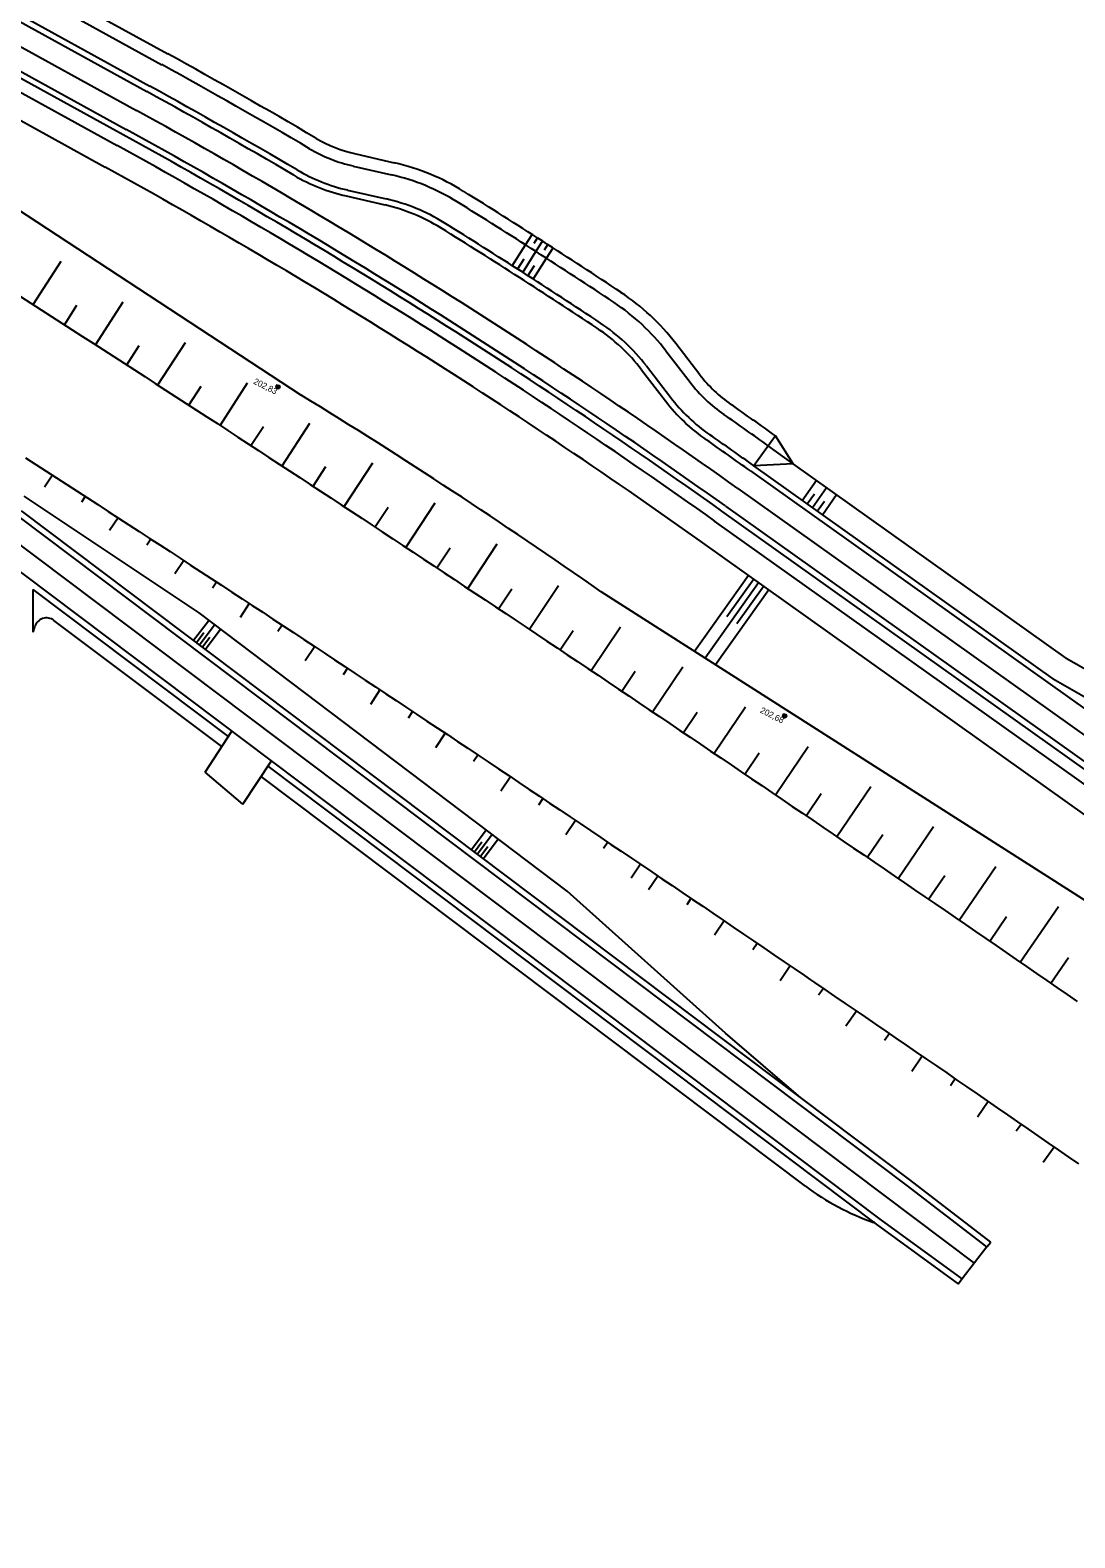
# Model space of a CAD drawing. Extents: x -552278 to -547230, y -1151007 to -1148251.
# Drawn here: x -550262.6 to -550177.8, y -1149150.6 to -1149028.3 of the extents above; entities that cross this region are included whole.
import ezdxf

# ---------------------------------------------------------------- set-up
doc = ezdxf.new("R2010")
doc.units = 0
doc.layers.add('SO221815_VYSKOPIS', color=7, linetype='Continuous')
doc.layers.add('u_trat navrh', color=7, linetype='Continuous')

# ---------------------------------------------------------------- blocks, each defined once
blk = doc.blocks.new('SO221824_VYSKOPIS')
at = {"layer": 'SO221815_VYSKOPIS'}
for p, q in [((1.2, -0.9), (-1.2, 0.9)), ((0.9, 1.2), (-0.9, -1.2)), ((0.9, 1.2), (0, 0)), ((0, 0), (1.2, -0.9))]:
    blk.add_line(p, q, dxfattribs=at)
blk.add_lwpolyline([(-0.9, -1.2), (0, 0), (-1.2, 0.9)], dxfattribs=at)
blk.add_circle((0, 0), 1.5, dxfattribs=at)
for start, end in [(145.362, 235.1538), (325.362, 55.1538)]:
    blk.add_arc((0, 0), 1.5, start, end, dxfattribs=at)

msp = doc.modelspace()

# ---------------------------------------------------------------- linework, layer by layer
at = {"layer": 'u_trat navrh'}
for p, q in [((-550460.23, -1148921.16), (-550253.98, -1149034.78)), ((-550461.07, -1148922.69), (-550254.82, -1149036.32)), ((-550461.8, -1148924.01), (-550255.55, -1149037.63)), ((-550462.76, -1148925.76), (-550256.51, -1149039.38)), ((-550441.65, -1148926.54), (-550251.93, -1149031.06)), ((-550442.86, -1148928.73), (-550253.14, -1149033.25)), ((-550442.62, -1148928.29), (-550252.89, -1149032.81)), ((-550371.01, -1148964.32), (-550251.45, -1149030.19)), ((-550236.18, -1149038.31), (-550233.06, -1149039.03)), ((-550268.44, -1149039.66), (-550240.61, -1149057.89)), ((-550236.4, -1149039.29), (-550233.28, -1149040)), ((-550236.85, -1149041.24), (-550233.73, -1149041.95)), ((-550236.96, -1149041.72), (-550233.84, -1149042.44)), ((-550222.41, -1149045.69), (-550221.87, -1149044.85)), ((-550223.48, -1149047.38), (-550222.41, -1149045.69)), ((-550221.71, -1149045.54), (-550221.44, -1149045.12)), ((-550221.56, -1149046.23), (-550221.02, -1149045.39)), ((-550220.87, -1149046.09), (-550220.6, -1149045.67)), ((-550220.72, -1149046.78), (-550220.17, -1149045.94)), ((-550262.36, -1149050.54), (-550260.09, -1149047)), ((-550223.06, -1149047.65), (-550222.52, -1149046.81)), ((-550222.64, -1149047.92), (-550221.56, -1149046.23)), ((-550222.22, -1149048.19), (-550221.68, -1149047.35)), ((-550221.8, -1149048.46), (-550220.72, -1149046.78)), ((-550259.83, -1149052.17), (-550258.81, -1149050.58)), ((-550257.3, -1149053.8), (-550255.05, -1149050.3)), ((-550254.77, -1149055.43), (-550253.76, -1149053.86)), ((-550252.25, -1149057.06), (-550250, -1149053.6)), ((-550211.02, -1149054.29), (-550209.06, -1149056.83)), ((-550210.22, -1149053.68), (-550208.27, -1149056.22)), ((-550213, -1149055.82), (-550211.04, -1149058.36)), ((-550212.6, -1149055.51), (-550210.65, -1149058.05)), ((-550249.73, -1149058.7), (-550248.72, -1149057.15)), ((-550247.2, -1149060.34), (-550244.96, -1149056.9)), ((-550244.69, -1149061.98), (-550243.68, -1149060.44)), ((-550242.17, -1149063.63), (-550239.9, -1149060.16)), ((-550202.13, -1149061.19), (-550203.87, -1149063.63)), ((-550200.68, -1149063.45), (-550202.71, -1149062)), ((-550200.68, -1149063.45), (-550202.13, -1149061.19)), ((-550260.81, -1149064.39), (-550261.45, -1149065.35)), ((-550239.65, -1149065.28), (-550238.61, -1149063.69)), ((-550237.14, -1149066.93), (-550234.79, -1149063.37)), ((-550204.16, -1149064.04), (-550115.93, -1149126.87)), ((-550200.68, -1149063.45), (-550203.87, -1149063.63)), ((-550179.6, -1149080.92), (-550203.87, -1149063.63)), ((-550178.52, -1149079.23), (-550200.68, -1149063.45)), ((-550205.18, -1149065.46), (-550087.55, -1149149.22)), ((-550199.95, -1149066.43), (-550198.79, -1149064.8)), ((-550199.13, -1149067.01), (-550197.97, -1149065.38)), ((-550248.9, -1149075.55), (-550263.1, -1149066.08)), ((-550258.14, -1149066.12), (-550258.44, -1149066.57)), ((-550234.63, -1149068.59), (-550233.56, -1149066.97)), ((-550232.12, -1149070.25), (-550229.73, -1149066.63)), ((-550206.19, -1149066.89), (-550088.57, -1149150.65)), ((-550199.54, -1149066.72), (-550198.96, -1149065.9)), ((-550198.73, -1149067.3), (-550198.15, -1149066.48)), ((-550198.32, -1149067.59), (-550197.16, -1149065.96)), ((-550191.52, -1149121.99), (-550263.62, -1149067.69)), ((-550191.22, -1149121.59), (-550263.32, -1149067.29)), ((-550255.47, -1149067.85), (-550256.16, -1149068.88)), ((-550144.16, -1149112.9), (-550207.06, -1149068.11)), ((-550185.98, -1149128.35), (-550264.54, -1149069.19)), ((-550193.63, -1149124.78), (-550265.73, -1149070.49)), ((-550252.81, -1149069.58), (-550253.13, -1149070.06)), ((-550229.61, -1149071.91), (-550228.53, -1149070.28)), ((-550227.1, -1149073.57), (-550224.71, -1149069.96)), ((-550140.95, -1149117.65), (-550208.22, -1149069.74)), ((-550250.15, -1149071.32), (-550250.87, -1149072.4)), ((-550247.49, -1149073.06), (-550247.82, -1149073.56)), ((-550204.3, -1149072.53), (-550208.69, -1149078.69)), ((-550203.49, -1149073.11), (-550207.84, -1149079.23)), ((-550203.89, -1149072.82), (-550206.08, -1149075.89)), ((-550246.51, -1149085.59), (-550262.36, -1149073.65)), ((-550262.36, -1149077.12), (-550262.36, -1149073.65)), ((-550224.6, -1149075.23), (-550223.52, -1149073.62)), ((-550222.1, -1149076.9), (-550219.72, -1149073.35)), ((-550166.24, -1149105.78), (-550216.28, -1149073.84)), ((-550202.67, -1149073.69), (-550207, -1149079.77)), ((-550203.08, -1149073.4), (-550205.25, -1149076.45)), ((-550219.03, -1149098.14), (-550248.9, -1149075.55)), ((-550244.83, -1149074.8), (-550245.58, -1149075.93)), ((-550262.36, -1149077.12), (-550262.24, -1149076.7)), ((-550247.06, -1149086.42), (-550260.68, -1149076.17)), ((-550248.15, -1149076.22), (-550249.35, -1149077.81)), ((-550247.67, -1149076.58), (-550248.87, -1149078.17)), ((-550242.17, -1149076.55), (-550242.52, -1149077.07)), ((-550217.09, -1149080.25), (-550214.71, -1149076.7)), ((-550248.51, -1149077.19), (-550249.11, -1149077.99)), ((-550248.03, -1149077.56), (-550248.63, -1149078.35)), ((-550247.19, -1149076.94), (-550248.39, -1149078.53)), ((-550219.59, -1149078.57), (-550218.54, -1149077)), ((-550239.52, -1149078.3), (-550240.29, -1149079.46)), ((-550178.52, -1149079.23), (-550169.76, -1149084.24)), ((-550236.87, -1149080.05), (-550237.22, -1149080.58)), ((-550214.6, -1149081.92), (-550213.51, -1149080.3)), ((-550212.1, -1149083.6), (-550209.63, -1149079.94)), ((-550179.6, -1149080.92), (-550170.84, -1149085.93)), ((-550234.22, -1149081.81), (-550235, -1149082.99)), ((-550231.57, -1149083.57), (-550231.92, -1149084.1)), ((-550209.6, -1149085.28), (-550208.48, -1149083.61)), ((-550207.11, -1149086.96), (-550204.55, -1149083.18)), ((-550248.41, -1149088.48), (-550246.23, -1149085.17)), ((-550228.92, -1149085.33), (-550229.71, -1149086.51)), ((-550202.13, -1149090.34), (-550199.47, -1149086.42)), ((-550245.34, -1149091.09), (-550243.03, -1149087.58)), ((-550226.28, -1149087.1), (-550226.63, -1149087.63)), ((-550204.62, -1149088.65), (-550203.45, -1149086.92)), ((-550245.34, -1149091.09), (-550248.41, -1149088.48)), ((-550199.69, -1149122.1), (-550243.86, -1149088.84)), ((-550193.93, -1149125.18), (-550243.3, -1149088)), ((-550223.64, -1149088.86), (-550224.42, -1149090.04)), ((-550199.64, -1149092.03), (-550198.42, -1149090.23)), ((-550197.15, -1149093.72), (-550194.39, -1149089.66)), ((-550221, -1149090.63), (-550221.35, -1149091.16)), ((-550218.36, -1149092.41), (-550219.13, -1149093.57)), ((-550225.59, -1149093.2), (-550226.79, -1149094.8)), ((-550225.11, -1149093.56), (-550226.31, -1149095.16)), ((-550224.63, -1149093.93), (-550225.83, -1149095.52)), ((-550194.67, -1149095.41), (-550193.4, -1149093.55)), ((-550192.18, -1149097.11), (-550189.31, -1149092.91)), ((-550225.95, -1149094.18), (-550226.55, -1149094.98)), ((-550225.47, -1149094.54), (-550226.07, -1149095.34)), ((-550215.72, -1149094.18), (-550216.07, -1149094.7)), ((-550213.09, -1149095.96), (-550213.84, -1149097.09)), ((-550187.22, -1149100.5), (-550184.23, -1149096.15)), ((-550211.67, -1149096.92), (-550212.42, -1149098.04)), ((-550189.7, -1149098.8), (-550188.38, -1149096.88)), ((-550206.19, -1149109.69), (-550219.03, -1149098.14)), ((-550208.98, -1149098.74), (-550209.33, -1149099.26)), ((-550182.26, -1149103.91), (-550179.15, -1149099.39)), ((-550206.29, -1149100.56), (-550207.08, -1149101.73)), ((-550184.74, -1149102.21), (-550183.37, -1149100.21)), ((-550203.61, -1149102.39), (-550203.97, -1149102.92)), ((-550179.78, -1149105.61), (-550178.35, -1149103.54)), ((-550200.92, -1149104.22), (-550201.75, -1149105.42)), ((-550198.24, -1149106.05), (-550198.62, -1149106.6)), ((-550195.56, -1149107.88), (-550196.41, -1149109.11)), ((-550200.06, -1149114.93), (-550206.19, -1149109.69)), ((-550192.88, -1149109.71), (-550193.27, -1149110.27)), ((-550190.21, -1149111.55), (-550191.07, -1149112.8)), ((-550187.53, -1149113.39), (-550187.92, -1149113.96)), ((-550184.86, -1149115.23), (-550185.73, -1149116.49)), ((-550182.19, -1149117.08), (-550182.58, -1149117.64)), ((-550179.51, -1149118.92), (-550180.39, -1149120.18)), ((-550184.96, -1149127.03), (-550191.52, -1149121.99)), ((-550184.66, -1149126.64), (-550191.22, -1149121.59)), ((-550194.1, -1149125.05), (-550194.16, -1149125.03)), ((-550187.25, -1149130.04), (-550193.92, -1149125.19)), ((-550186.96, -1149129.63), (-550193.63, -1149124.78)), ((-550184.96, -1149127.03), (-550184.66, -1149126.64)), ((-550184.96, -1149127.03), (-550186.96, -1149129.63)), ((-550186.96, -1149129.63), (-550187.27, -1149130.03))]:
    msp.add_line(p, q, dxfattribs=at)
for points in [[(-550255.07, -1149036.76), (-550461.31, -1148923.13)], [(-550263.4, -1149049.87), (-550262.56, -1149050.41), (-550261.72, -1149050.96), (-550260.88, -1149051.5), (-550260.03, -1149052.04), (-550259.19, -1149052.58), (-550258.35, -1149053.12), (-550257.51, -1149053.66), (-550256.67, -1149054.21), (-550255.82, -1149054.75), (-550254.98, -1149055.29), (-550254.14, -1149055.84), (-550253.3, -1149056.38), (-550252.46, -1149056.93), (-550251.62, -1149057.47), (-550250.78, -1149058.02), (-550249.94, -1149058.56), (-550249.1, -1149059.11), (-550248.26, -1149059.65), (-550247.42, -1149060.2), (-550246.58, -1149060.75), (-550245.75, -1149061.29), (-550244.91, -1149061.84), (-550244.07, -1149062.39), (-550243.23, -1149062.94), (-550242.39, -1149063.48), (-550241.56, -1149064.03), (-550240.72, -1149064.58), (-550239.88, -1149065.13), (-550239.04, -1149065.68), (-550238.21, -1149066.23), (-550237.37, -1149066.78), (-550236.53, -1149067.33), (-550235.7, -1149067.88), (-550234.86, -1149068.43), (-550234.03, -1149068.98), (-550233.19, -1149069.54), (-550232.36, -1149070.09), (-550231.52, -1149070.64), (-550230.69, -1149071.19), (-550229.85, -1149071.75), (-550229.02, -1149072.3), (-550228.18, -1149072.85), (-550227.35, -1149073.41), (-550226.51, -1149073.96), (-550225.68, -1149074.51), (-550224.85, -1149075.07), (-550224.01, -1149075.62), (-550223.18, -1149076.18), (-550222.35, -1149076.73), (-550221.51, -1149077.29), (-550220.68, -1149077.85), (-550219.85, -1149078.4), (-550219.02, -1149078.96), (-550218.19, -1149079.52), (-550217.35, -1149080.07), (-550216.52, -1149080.63), (-550215.69, -1149081.19), (-550214.86, -1149081.75), (-550214.03, -1149082.3), (-550213.2, -1149082.86), (-550212.37, -1149083.42), (-550211.54, -1149083.98), (-550210.71, -1149084.54), (-550209.88, -1149085.1), (-550209.05, -1149085.66), (-550208.22, -1149086.22), (-550207.39, -1149086.78), (-550206.56, -1149087.34), (-550205.73, -1149087.9), (-550204.9, -1149088.46), (-550204.07, -1149089.02), (-550203.24, -1149089.58), (-550202.41, -1149090.14), (-550201.58, -1149090.71), (-550200.76, -1149091.27), (-550199.93, -1149091.83), (-550199.1, -1149092.39), (-550198.27, -1149092.96), (-550197.44, -1149093.52), (-550196.62, -1149094.08), (-550195.79, -1149094.65), (-550194.96, -1149095.21), (-550194.14, -1149095.77), (-550193.31, -1149096.34), (-550192.48, -1149096.9), (-550191.66, -1149097.47), (-550190.83, -1149098.03), (-550190, -1149098.6), (-550189.18, -1149099.16), (-550188.35, -1149099.73), (-550187.53, -1149100.29), (-550186.7, -1149100.86), (-550185.88, -1149101.43), (-550185.05, -1149101.99), (-550184.22, -1149102.56), (-550183.4, -1149103.13), (-550182.58, -1149103.69), (-550181.75, -1149104.26), (-550180.93, -1149104.83), (-550180.1, -1149105.39), (-550179.28, -1149105.96), (-550178.45, -1149106.53), (-550177.63, -1149107.1)], [(-550262.99, -1149062.98), (-550262.15, -1149063.52), (-550261.31, -1149064.06), (-550260.48, -1149064.6), (-550259.64, -1149065.15), (-550258.8, -1149065.69), (-550257.96, -1149066.23), (-550257.12, -1149066.77), (-550256.28, -1149067.32), (-550255.45, -1149067.86), (-550254.61, -1149068.41), (-550253.77, -1149068.95), (-550252.94, -1149069.5), (-550252.1, -1149070.04), (-550251.26, -1149070.59), (-550250.43, -1149071.13), (-550249.59, -1149071.68), (-550248.76, -1149072.23), (-550247.92, -1149072.77), (-550247.08, -1149073.32), (-550246.25, -1149073.87), (-550245.41, -1149074.42), (-550244.58, -1149074.97), (-550243.74, -1149075.51), (-550242.91, -1149076.06), (-550242.08, -1149076.61), (-550241.24, -1149077.16), (-550240.41, -1149077.71), (-550239.57, -1149078.26), (-550238.74, -1149078.81), (-550237.91, -1149079.36), (-550237.07, -1149079.92), (-550236.24, -1149080.47), (-550235.41, -1149081.02), (-550234.58, -1149081.57), (-550233.74, -1149082.12), (-550232.91, -1149082.68), (-550232.08, -1149083.23), (-550231.25, -1149083.78), (-550230.42, -1149084.34), (-550229.59, -1149084.89), (-550228.75, -1149085.44), (-550227.92, -1149086), (-550227.09, -1149086.55), (-550226.26, -1149087.11), (-550225.43, -1149087.66), (-550224.6, -1149088.22), (-550223.77, -1149088.77), (-550222.94, -1149089.33), (-550222.11, -1149089.89), (-550221.28, -1149090.44), (-550220.45, -1149091), (-550219.62, -1149091.56), (-550218.79, -1149092.11), (-550217.97, -1149092.67), (-550217.14, -1149093.23), (-550216.31, -1149093.79), (-550215.48, -1149094.35), (-550214.65, -1149094.9), (-550213.82, -1149095.46), (-550213, -1149096.02), (-550212.17, -1149096.58), (-550211.34, -1149097.14), (-550210.51, -1149097.7), (-550209.69, -1149098.26), (-550208.86, -1149098.82), (-550208.03, -1149099.38), (-550207.21, -1149099.94), (-550206.38, -1149100.5), (-550205.55, -1149101.07), (-550204.73, -1149101.63), (-550203.9, -1149102.19), (-550203.07, -1149102.75), (-550202.25, -1149103.31), (-550201.42, -1149103.88), (-550200.6, -1149104.44), (-550199.77, -1149105), (-550199.28, -1149105.34), (-550198.95, -1149105.57), (-550198.12, -1149106.13), (-550197.3, -1149106.69), (-550196.47, -1149107.26), (-550195.65, -1149107.82), (-550194.82, -1149108.39), (-550194, -1149108.95), (-550193.17, -1149109.52), (-550192.35, -1149110.08), (-550191.53, -1149110.65), (-550190.7, -1149111.21), (-550189.88, -1149111.78), (-550189.06, -1149112.34), (-550188.23, -1149112.91), (-550187.41, -1149113.48), (-550186.59, -1149114.04), (-550185.76, -1149114.61), (-550184.94, -1149115.18), (-550184.12, -1149115.74), (-550183.29, -1149116.31), (-550182.47, -1149116.88), (-550181.65, -1149117.45), (-550180.83, -1149118.01), (-550180.01, -1149118.58), (-550179.18, -1149119.15), (-550178.36, -1149119.72), (-550177.54, -1149120.29)], [(-550102.81, -1149141.12), (-550132.81, -1149119.76), (-550142.58, -1149112.8), (-550206.48, -1149067.3)]]:
    msp.add_lwpolyline(points, dxfattribs=at)
for centre, radius, start, end in [((-550495.24, -1149472.72), 505.25, 59.5816, 61.1494), ((-550495.24, -1149472.72), 504.25, 59.5816, 61.1494), ((-550495.24, -1149472.72), 501.75, 59.5816, 61.1494), ((-550495.24, -1149472.72), 502.25, 59.5816, 61.1494), ((-550495.24, -1149472.72), 500, 54.5401, 61.1494), ((-550495.24, -1149472.72), 498.25, 54.5401, 61.1494), ((-550495.24, -1149472.72), 496.75, 54.5401, 61.1494), ((-550495.24, -1149472.72), 497.75, 54.5401, 61.1494), ((-550233.61, -1149027.1), 11.5, 239.5816, 257.0757), ((-550233.61, -1149027.1), 12.5, 239.5816, 257.0757), ((-550495.24, -1149472.72), 494.75, 54.5401, 61.1494), ((-550233.61, -1149027.1), 15, 239.5816, 257.0757), ((-550233.61, -1149027.1), 14.5, 239.5816, 257.0757), ((-550237.19, -1149057.06), 17.5, 58.1674, 77.0757), ((-550237.19, -1149057.06), 18.5, 58.1674, 77.0757), ((-550237.19, -1149057.06), 15, 58.1674, 77.0757), ((-550237.19, -1149057.06), 15.5, 58.1674, 77.0757), ((-550495.24, -1149472.72), 506.75, 56.4553, 58.1674), ((-550495.24, -1149472.72), 507.75, 56.4553, 58.1674), ((-550495.24, -1149472.72), 504.25, 56.4553, 58.1674), ((-550495.24, -1149472.72), 504.75, 56.4553, 58.1674), ((-550224.89, -1149064.96), 18.5, 37.547, 56.4553), ((-550224.89, -1149064.96), 17.5, 37.547, 56.4553), ((-550224.89, -1149064.96), 15.5, 37.547, 56.4553), ((-550224.89, -1149064.96), 15, 37.547, 56.4553), ((-550199.15, -1149049.22), 12.5, 217.547, 235.0411), ((-550199.15, -1149049.22), 11.5, 217.547, 235.0411), ((-550495.24, -1149472.72), 486.75, 55.0326, 58.4573), ((-550199.15, -1149049.22), 15, 217.547, 235.0411), ((-550199.15, -1149049.22), 14.5, 217.547, 235.0411), ((-550495.24, -1149472.72), 504.25, 54.5401, 55.0411), ((-550495.24, -1149472.72), 505.25, 54.5401, 55.0411), ((-550495.24, -1149472.72), 501.75, 54.5401, 55.0411), ((-550495.24, -1149472.72), 502.25, 54.5401, 55.0411), ((-550261.28, -1149076.97), 1, 53.0187, 164.4118), ((-550187.66, -1149106.12), 20, 233.0187, 251.0281)]:
    msp.add_arc(centre, radius, start, end, dxfattribs=at)

# ---------------------------------------------------------------- block references
at = {"layer": 'u_trat navrh', "xscale": 0.1, "yscale": 0.09999999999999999, "rotation": -31.851985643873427}
for p in [(-550242.5, -1149057.22), (-550201.38, -1149083.92)]:
    msp.add_blockref('SO221824_VYSKOPIS', p, dxfattribs=at)

# ---------------------------------------------------------------- texts
at = {"layer": 'u_trat navrh'}
for s, p in [('202,83', (-550244.54, -1149056.93)), ('202,68', (-550203.42, -1149083.63))]:
    msp.add_text(s, height=0.5, rotation=333.2568, dxfattribs=at).set_placement(p)

doc.saveas('drawing.dxf')
